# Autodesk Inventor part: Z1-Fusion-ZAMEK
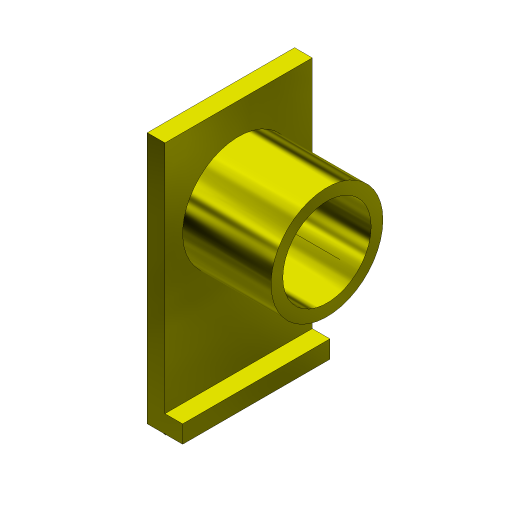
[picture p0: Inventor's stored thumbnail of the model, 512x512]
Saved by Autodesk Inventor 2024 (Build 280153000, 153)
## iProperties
Created: 2023-03
Part Number: Z1-Fusion-ZAMEK
Material: 10HA
Document SubType Name: Modeling
Designer: Andrzej Jaskulski
Density: 7.73 g/cm^3
Appearance: Częściowo polerowany
Checked By: A.J.
Engr Approved By: Andrzej Jaskulski
Mfg Approved By: Andrzej Jaskulski
Authority: A.J.
Company: ATC
Title: A.J.: Kurs R2024-MEP
Author: Andrzej Jaskulski
Revision Number: 1/24
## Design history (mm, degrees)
sketch "WSPÓLny"
  geometry: L1 (0, 0)-(25, 0); L2 (25, 0)-(25, 42.8); L3 (25, 42.8)-(0, 42.8); L4 (0, 42.8)-(0, 0); L5 (0, 3)-(25, 3); C1 r 9.5 at (12.5, 28); C2 r 7.5 at (12.5, 28); 1 further point
  constraints: 10 end point, 2 centre point, 2 parallel, 2 perpendicular, 2 point on line, 1 coincident, 1 horizontal, 1 midpoint, 1 vertical alignment, 1 other
  dimensions: "d0" = 25 distance of L1.start L1.end (= Y); "d1" = 3 distance between parallel lines of L5 L1 (= X); "d2" = 25 distance from line of C1.centre L5 (derived); "d3" = 14.8 distance from line of C1.centre L3; "d4" = 19 diameter of C1; "d5" = 15 diameter of C2; "d12" = 28 distance from line of C1.centre L1
extrude "PŁYTA" new body sketch "WSPÓLny" distance "d6" = 3 (= X); taper "d7" = 0 deg
extrude "Stopka" join sketch "WSPÓLny" distance "d8" = 3 (computed from X); taper "d9" = 0 deg
extrude "Wyciągnięcie proste3" join sketch "WSPÓLny" distance "d10" = 15; taper "d11" = 0 deg
node "Oś konstrukcyjna1"
node "Bryła1"
other parameters: "X" = 3 [user parameter; used in 3 equation terms], "Y" = 25 [user parameter; used in 1 equation term]
